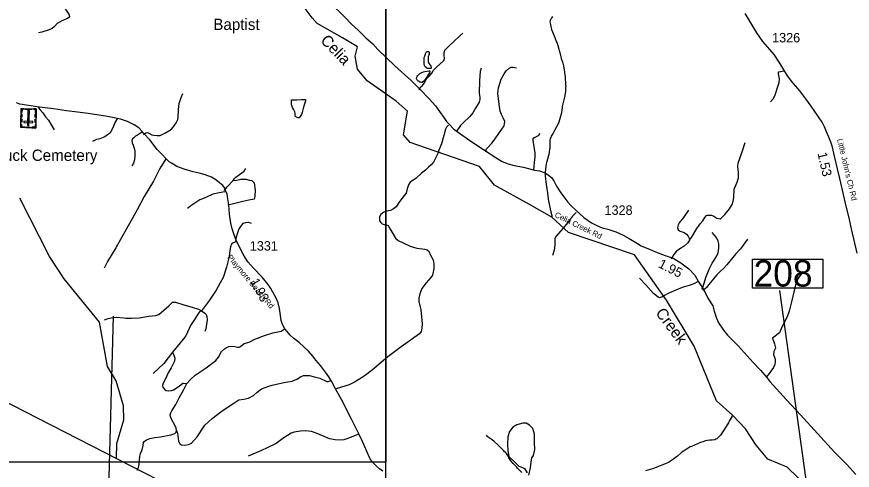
# Model space of a CAD drawing. Extents: x 1159738 to 1321356, y 736314 to 882035.
# Drawn here: x 1208685 to 1219753, y 778002 to 784003 of the extents above; entities that cross this region are included whole.
import ezdxf

# ---------------------------------------------------------------- set-up
doc = ezdxf.new("R2010")
doc.units = 0
for name, color, linetype in [('Exist Boundary Political CountyLine', 7, 'Continuous'), ('Exist Cultural Cemetery CELL', 7, 'Continuous'), ('Exist Cultural Cemetery Label', 7, 'Continuous'), ('Exist Cultural Church Label', 7, 'Continuous'), ('Exist Hydrographic Creek Single Shore', 7, 'Continuous'), ('Exist Hydrographic Creek Single Shore Label', 7, 'Continuous'), ('Exist Hydrographic Misc Water Feature', 7, 'Continuous'), ('Exist Road Non-System Type 51', 7, 'Continuous'), ('Exist Road Secondary Mileage Hundredths English Label', 7, 'Continuous'), ('Exist Road Secondary Structure Standard Bridge Number Label', 7, 'Continuous'), ('Exist Road Secondary Type 51 Attributed', 7, 'Continuous'), ('Exist Road Secondary Type 51 Label', 7, 'Continuous'), ('Exist Road Secondary Type 51 Number Label', 7, 'Continuous'), ('Map Preparation Inset Cut Line', 7, 'Continuous'), ('Map Preparation Longitude Latitude Lines', 7, 'Continuous')]:
    doc.layers.add(name, color=color, linetype=linetype)

msp = doc.modelspace()

# ---------------------------------------------------------------- linework, layer by layer
at = {"layer": 'Exist Boundary Political CountyLine'}
msp.add_lwpolyline([(1221685, 768580), (1219889, 769468), (1217945, 774092), (1206157, 780126), (1197315, 784354)], dxfattribs=at)
at = {"layer": 'Exist Cultural Cemetery CELL'}
for points in [[(1208937, 782530), (1208738, 782535), (1208744, 782789), (1208943, 782784)], [(1208777, 782789), (1208777, 782777), (1208755, 782778), (1208754, 782737), (1208743, 782738), (1208744, 782789)], [(1208886, 782774), (1208801, 782777), (1208801, 782788), (1208886, 782786)], [(1208910, 782785), (1208910, 782774), (1208932, 782773), (1208931, 782733), (1208942, 782733), (1208943, 782784)], [(1208754, 782717), (1208753, 782674), (1208741, 782674), (1208742, 782717)], [(1208829, 782562), (1208847, 782561), (1208852, 782764), (1208834, 782765)], [(1208942, 782715), (1208940, 782671), (1208929, 782672), (1208930, 782715)], [(1208739, 782578), (1208750, 782578), (1208749, 782546), (1208790, 782545), (1208790, 782534), (1208738, 782535)], [(1208752, 782651), (1208751, 782608), (1208740, 782608), (1208741, 782651)], [(1208898, 782599), (1208898, 782618), (1208781, 782621), (1208780, 782602)], [(1208938, 782573), (1208927, 782574), (1208926, 782541), (1208885, 782542), (1208885, 782531), (1208937, 782530)], [(1208940, 782647), (1208939, 782604), (1208927, 782604), (1208928, 782648)], [(1208863, 782532), (1208811, 782533), (1208811, 782544), (1208863, 782543)]]:
    msp.add_lwpolyline(points, close=True, dxfattribs=at)
at = {"layer": 'Exist Hydrographic Creek Single Shore'}
for points in [[(1212599, 783989), (1212519, 784096), (1212430, 784222), (1212427, 784288), (1212400, 784408), (1212418, 784549)], [(1219041, 777899), (1218890, 778042), (1218634, 778149), (1218481, 778332), (1218340, 778550), (1218168, 778730), (1217954, 778922), (1217660, 779644), (1217294, 780252), (1216867, 780851), (1215993, 781149), (1215772, 781352), (1215476, 781519), (1215012, 781772), (1214815, 782022), (1213897, 782338), (1213808, 782439), (1213861, 782753), (1213712, 782886), (1213327, 783154), (1213198, 783308), (1213169, 783481), (1213201, 783606), (1213000, 783722), (1212664, 783912), (1212599, 783989)]]:
    msp.add_lwpolyline(points, dxfattribs=at)
at = {"layer": 'Exist Hydrographic Misc Water Feature'}
for points in [[(1215782, 784007), (1215774, 783993), (1215763, 783977), (1215759, 783969), (1215753, 783951), (1215748, 783934), (1215750, 783917), (1215757, 783901)], [(1215757, 783901), (1215757, 783897), (1215770, 783835), (1215781, 783803), (1215799, 783757), (1215812, 783727), (1215837, 783666), (1215843, 783651), (1215848, 783636), (1215853, 783620), (1215867, 783574), (1215871, 783558), (1215882, 783510), (1215897, 783448), (1215902, 783433), (1215909, 783418), (1215918, 783387), (1215926, 783355), (1215932, 783323), (1215935, 783307), (1215942, 783260), (1215948, 783212), (1215956, 783099), (1215957, 783083), (1215956, 783066), (1215956, 783050), (1215955, 783033), (1215954, 783017), (1215949, 782985), (1215939, 782938), (1215912, 782813), (1215911, 782797), (1215906, 782765), (1215899, 782733), (1215887, 782686), (1215874, 782639), (1215864, 782609), (1215854, 782578), (1215815, 782506), (1215790, 782464), (1215774, 782435), (1215766, 782421), (1215759, 782406), (1215753, 782391), (1215748, 782359), (1215748, 782343), (1215747, 782326), (1215747, 782310), (1215747, 782294), (1215746, 782277), (1215746, 782261), (1215744, 782245), (1215740, 782212), (1215735, 782181), (1215731, 782165), (1215717, 782119), (1215707, 782089), (1215703, 782074), (1215699, 782058), (1215693, 782027), (1215686, 781946), (1215685, 781897), (1215698, 781785), (1215702, 781753), (1215705, 781737), (1215708, 781721), (1215710, 781705), (1215715, 781673), (1215721, 781626), (1215724, 781594), (1215731, 781562), (1215737, 781530), (1215744, 781499), (1215762, 781421), (1215774, 781373), (1215772, 781352)], [(1214089, 783480), (1214100, 783510), (1214108, 783528), (1214114, 783537), (1214121, 783542), (1214132, 783544), (1214141, 783542), (1214146, 783540), (1214148, 783536), (1214149, 783526), (1214148, 783515), (1214147, 783506), (1214142, 783492), (1214137, 783478), (1214134, 783464), (1214133, 783444), (1214133, 783413), (1214136, 783403), (1214140, 783391), (1214148, 783380), (1214162, 783363), (1214170, 783350), (1214174, 783339), (1214174, 783330), (1214173, 783320), (1214172, 783317), (1214168, 783317), (1214126, 783317), (1214123, 783319), (1214111, 783328), (1214096, 783340), (1214092, 783348), (1214087, 783359), (1214083, 783381), (1214080, 783399), (1214080, 783435), (1214082, 783455), (1214084, 783465), (1214089, 783480)], [(1213997, 783225), (1214012, 783239), (1214026, 783251), (1214051, 783266), (1214071, 783275), (1214092, 783278), (1214121, 783283), (1214147, 783287), (1214155, 783286), (1214157, 783275), (1214151, 783260), (1214134, 783232), (1214111, 783197), (1214096, 783174), (1214077, 783151), (1214062, 783136), (1214054, 783133), (1214045, 783134), (1214031, 783138), (1214009, 783148), (1214000, 783153), (1213994, 783160), (1213988, 783167), (1213984, 783176), (1213981, 783186), (1213981, 783194), (1213983, 783203), (1213988, 783214), (1213997, 783225)], [(1212325, 782902), (1212397, 782905), (1212455, 782907), (1212509, 782906), (1212508, 782890), (1212506, 782877), (1212497, 782846), (1212485, 782806), (1212474, 782769), (1212464, 782737), (1212455, 782707), (1212449, 782694), (1212440, 782682), (1212424, 782667), (1212418, 782665), (1212412, 782664), (1212401, 782668), (1212383, 782679), (1212377, 782684), (1212374, 782688), (1212374, 782695), (1212375, 782718), (1212373, 782727), (1212367, 782745), (1212361, 782761), (1212351, 782779), (1212338, 782802), (1212329, 782826), (1212324, 782836), (1212323, 782847), (1212325, 782902)], [(1210006, 778156), (1210012, 778356), (1210104, 778669), (1210100, 778853), (1210001, 779183), (1209889, 779376), (1209780, 779962), (1209312, 780536), (1209120, 780832), (1208724, 781602)], [(1218168, 778730), (1218160, 778716), (1218136, 778673), (1218128, 778659), (1218120, 778644), (1218112, 778630), (1218104, 778616), (1218043, 778520), (1218006, 778466), (1217996, 778453), (1217985, 778442), (1217973, 778431), (1217961, 778419), (1217946, 778413), (1217931, 778406), (1217899, 778401), (1217883, 778400), (1217867, 778398), (1217804, 778389), (1217788, 778384), (1217773, 778380), (1217743, 778367), (1217622, 778317), (1217607, 778310), (1217593, 778303), (1217578, 778295), (1217524, 778259), (1217510, 778250), (1217485, 778231), (1217436, 778188), (1217424, 778178), (1217386, 778148), (1217346, 778120), (1217318, 778104), (1217273, 778085), (1217243, 778074), (1217197, 778058), (1217153, 778037), (1217108, 778020), (1217014, 777994)], [(1215198, 778183), (1215171, 778223), (1215160, 778235), (1215148, 778247), (1215137, 778259), (1215125, 778270), (1215079, 778316), (1215068, 778328), (1215057, 778340), (1215008, 778383), (1214984, 778405), (1214971, 778415), (1214958, 778424), (1214944, 778433), (1214930, 778441), (1214917, 778451), (1214906, 778464)], [(1215376, 777970), (1215330, 778018), (1215319, 778030), (1215308, 778042), (1215297, 778054), (1215286, 778066), (1215274, 778078), (1215263, 778090), (1215230, 778126), (1215221, 778140), (1215213, 778154), (1215205, 778168), (1215198, 778183)]]:
    msp.add_lwpolyline(points, dxfattribs=at)
at = {"layer": 'Exist Road Non-System Type 51'}
for points in [[(1209221, 785242), (1209191, 785139), (1209161, 785011), (1209134, 784925), (1209139, 784802), (1209177, 784528), (1209215, 784373), (1209272, 784191), (1209351, 784066), (1209381, 784026), (1209384, 783998), (1209348, 783974), (1209283, 783950), (1209221, 783911), (1209186, 783872), (1209156, 783845), (1209115, 783828), (1209018, 783798), (1208971, 783788)], [(1214015, 783034), (1214040, 783076), (1214057, 783090), (1214085, 783129), (1214115, 783180), (1214157, 783224), (1214184, 783254), (1214206, 783294), (1214243, 783333), (1214343, 783424), (1214352, 783448), (1214347, 783495), (1214348, 783529), (1214357, 783560), (1214399, 783603), (1214556, 783750), (1214596, 783785)], [(1214898, 782215), (1214903, 782240), (1214909, 782256), (1214931, 782278), (1214978, 782328), (1215022, 782387), (1215082, 782470), (1215140, 782559), (1215148, 782587), (1215149, 782615), (1215130, 782663), (1215107, 782710), (1215089, 782751), (1215074, 782848), (1215058, 782991), (1215066, 783063), (1215102, 783176), (1215142, 783249), (1215170, 783289), (1215210, 783324), (1215235, 783334), (1215259, 783334), (1215304, 783327)], [(1214838, 783322), (1214823, 783277), (1214817, 783157), (1214810, 782988), (1214820, 782939), (1214819, 782908), (1214809, 782871), (1214763, 782791), (1214727, 782732), (1214686, 782684), (1214598, 782600), (1214565, 782563), (1214506, 782480)], [(1218671, 782878), (1218706, 782915), (1218730, 782967), (1218756, 783052), (1218784, 783133), (1218790, 783182), (1218778, 783226), (1218774, 783245), (1218777, 783272), (1218800, 783276), (1218845, 783289)], [(1210363, 782440), (1210376, 782453), (1210394, 782465), (1210415, 782469), (1210435, 782460), (1210476, 782438), (1210502, 782435), (1210543, 782431), (1210583, 782433), (1210645, 782461), (1210700, 782494), (1210736, 782517), (1210772, 782561), (1210798, 782601), (1210818, 782642), (1210823, 782672), (1210827, 782775), (1210838, 782856), (1210861, 782936), (1210886, 782985)], [(1208970, 782803), (1208996, 782769), (1209030, 782729), (1209064, 782676), (1209104, 782633), (1209138, 782582), (1209181, 782506)], [(1209691, 782358), (1209744, 782381), (1209790, 782391), (1209833, 782411), (1209850, 782419), (1209889, 782445), (1209925, 782473), (1209964, 782539), (1209990, 782602), (1210020, 782650)], [(1214406, 782570), (1214376, 782542), (1214364, 782514), (1214341, 782433), (1214310, 782319), (1214276, 782238), (1214261, 782194), (1214204, 782080), (1214176, 782045), (1214139, 782010), (1214101, 781973), (1214046, 781931), (1213978, 781866), (1213931, 781836), (1213898, 781813), (1213873, 781778), (1213856, 781727), (1213843, 781669), (1213815, 781638), (1213748, 781543), (1213713, 781489), (1213677, 781461), (1213636, 781441), (1213585, 781429), (1213548, 781415), (1213508, 781385), (1213492, 781354), (1213492, 781304), (1213506, 781282), (1213524, 781264), (1213550, 781252), (1213582, 781249), (1213605, 781240), (1213619, 781212), (1213657, 781147), (1213703, 781072), (1213738, 781044), (1213806, 781010), (1213896, 780968), (1213983, 780942), (1214091, 780928), (1214122, 780919), (1214143, 780900), (1214166, 780850), (1214199, 780784), (1214210, 780729), (1214208, 780668), (1214191, 780584), (1214171, 780551), (1214110, 780481), (1214050, 780405), (1214024, 780338), (1214010, 780277), (1214012, 780234), (1214036, 780125), (1214054, 779938), (1214052, 779882), (1214041, 779838), (1214021, 779806)], [(1210338, 782470), (1210285, 782436), (1210258, 782421), (1210236, 782402), (1210220, 782387), (1210209, 782364), (1210212, 782336), (1210229, 782302), (1210242, 782265), (1210251, 782225), (1210251, 782163), (1210245, 782110), (1210232, 782064), (1210208, 782030)], [(1215533, 781974), (1215539, 782021), (1215544, 782074), (1215552, 782147), (1215554, 782200), (1215539, 782280), (1215526, 782368), (1215527, 782387), (1215533, 782402), (1215571, 782418), (1215598, 782432), (1215617, 782456)], [(1217596, 781047), (1217625, 781080), (1217695, 781202), (1217736, 781263), (1217775, 781304), (1217801, 781345), (1217820, 781371), (1217834, 781376), (1217857, 781379), (1217886, 781376), (1217921, 781364), (1217959, 781338), (1217987, 781331), (1218005, 781329), (1218017, 781336), (1218064, 781386), (1218127, 781461), (1218163, 781519), (1218175, 781564), (1218184, 781611), (1218188, 781721), (1218226, 781815), (1218247, 781869), (1218245, 781940), (1218236, 782019), (1218242, 782066), (1218299, 782230), (1218334, 782340)], [(1210659, 782124), (1210582, 781995), (1210495, 781829), (1210374, 781624), (1210279, 781446), (1209996, 780946), (1209886, 780762), (1209845, 780675)], [(1211434, 781705), (1211473, 781753), (1211551, 781837), (1211564, 781857), (1211589, 781880), (1211635, 781914), (1211699, 781961), (1211720, 781995)], [(1211551, 781837), (1211601, 781840), (1211653, 781854), (1211690, 781854), (1211722, 781854), (1211763, 781842), (1211797, 781835), (1211829, 781803), (1211845, 781710), (1211840, 781624), (1211829, 781590), (1211760, 781574), (1211679, 781556), (1211540, 781521), (1211480, 781508)], [(1211441, 781687), (1211366, 781674), (1211284, 781653), (1211188, 781610), (1211111, 781578), (1210992, 781499), (1210949, 781467)], [(1217584, 781445), (1217516, 781347), (1217458, 781277), (1217446, 781249), (1217439, 781213), (1217446, 781185), (1217474, 781167), (1217528, 781146), (1217557, 781124), (1217580, 781099), (1217592, 781073), (1217596, 781047), (1217575, 781012), (1217528, 780967), (1217467, 780930), (1217422, 780895), (1217388, 780857), (1217354, 780794)], [(1216097, 781413), (1216049, 781362), (1215979, 781274), (1215923, 781205), (1215828, 781094), (1215812, 781064), (1215813, 781025), (1215813, 780980), (1215802, 780912), (1215780, 780845)], [(1211587, 781024), (1211596, 781089), (1211610, 781135), (1211626, 781189), (1211662, 781242), (1211689, 781272), (1211721, 781279), (1211753, 781283), (1211792, 781271)], [(1217761, 780397), (1217777, 780434), (1217814, 780553), (1217857, 780661), (1217897, 780742), (1217931, 780793), (1217960, 780839), (1217976, 780879), (1217984, 780939), (1217984, 780998), (1217975, 781034), (1217957, 781072), (1217929, 781111), (1217898, 781147)], [(1211587, 781024), (1211552, 781011), (1211531, 780993), (1211516, 780960), (1211509, 780909), (1211500, 780829), (1211465, 780689), (1211418, 780551), (1211380, 780480), (1211326, 780386), (1211238, 780251), (1211133, 780112)], [(1218365, 781059), (1218274, 780933), (1218206, 780862), (1218090, 780721), (1218053, 780678), (1218000, 780628), (1217956, 780585), (1217854, 780459), (1217823, 780420), (1217810, 780407), (1217772, 780382)], [(1219102, 780631), (1219057, 780574), (1219031, 780533), (1219007, 780471), (1218968, 780322), (1218952, 780246), (1218915, 780107), (1218890, 780032), (1218822, 779896), (1218791, 779818), (1218696, 779751)], [(1217702, 780493), (1217652, 780469), (1217592, 780445), (1217500, 780422), (1217394, 780378), (1217312, 780340), (1217265, 780314), (1217240, 780296), (1217199, 780282), (1217183, 780293), (1217122, 780340), (1217017, 780457), (1216934, 780544)], [(1209846, 779991), (1209894, 780009), (1209958, 780025), (1210003, 780028), (1210105, 780018), (1210131, 780014), (1210204, 780016), (1210308, 780019), (1210383, 780030), (1210434, 780039), (1210477, 780043), (1210527, 780050), (1210565, 780064), (1210698, 780178), (1210750, 780226), (1210766, 780228), (1210789, 780228), (1210900, 780191), (1211010, 780160), (1211092, 780132), (1211133, 780112)], [(1211133, 780112), (1211107, 780096), (1211076, 780055), (1211048, 780010), (1211030, 779984), (1210986, 779916), (1210929, 779790), (1210911, 779761), (1210750, 779564), (1210635, 779416), (1210492, 779284)], [(1211133, 780112), (1211178, 780082), (1211196, 780062), (1211205, 780037), (1211208, 779993), (1211192, 779873), (1211176, 779838)], [(1210940, 779151), (1210992, 779209), (1211049, 779258), (1211196, 779357), (1211324, 779452), (1211356, 779499), (1211399, 779574), (1211435, 779607), (1211464, 779627), (1211495, 779640), (1211531, 779644), (1211573, 779640), (1211609, 779630), (1211631, 779631), (1211649, 779640), (1211699, 779678), (1211765, 779697), (1211840, 779735), (1211969, 779785), (1212077, 779818), (1212187, 779844), (1212229, 779867)], [(1214021, 779806), (1213779, 779637), (1213601, 779502), (1213396, 779330), (1213289, 779248), (1213158, 779167), (1213088, 779133), (1212929, 779085), (1212899, 779073)], [(1218696, 779751), (1218724, 779676), (1218736, 779622), (1218732, 779609), (1218713, 779571), (1218711, 779532), (1218730, 779471), (1218732, 779435), (1218726, 779400), (1218711, 779360), (1218638, 779264), (1218607, 779228)], [(1210750, 779564), (1210771, 779511), (1210778, 779485), (1210773, 779447), (1210729, 779355), (1210690, 779291), (1210655, 779210), (1210623, 779152), (1210616, 779125), (1210622, 779100), (1210642, 779074), (1210666, 779059), (1210696, 779053), (1210736, 779056), (1210760, 779066), (1210836, 779116), (1210886, 779152), (1210896, 779155), (1210940, 779151)], [(1210801, 778528), (1210814, 778491), (1210829, 778386), (1210846, 778353), (1210868, 778337), (1210910, 778335), (1210962, 778341), (1211002, 778360), (1211076, 778445), (1211176, 778598), (1211275, 778687), (1211408, 778789), (1211559, 778890), (1211629, 778935), (1211694, 778944), (1211755, 778955), (1211822, 778990), (1211868, 779033), (1211928, 779080), (1212024, 779114), (1212070, 779128), (1212144, 779147), (1212250, 779168), (1212334, 779180), (1212366, 779192), (1212397, 779206), (1212444, 779240), (1212485, 779255), (1212523, 779257), (1212562, 779254), (1212612, 779242), (1212701, 779221), (1212794, 779178), (1212812, 779177), (1212836, 779187)], [(1210282, 778005), (1210296, 778039), (1210306, 778076), (1210315, 778190), (1210326, 778223), (1210347, 778274), (1210358, 778331), (1210363, 778367), (1210371, 778381), (1210406, 778405), (1210450, 778423), (1210513, 778434), (1210589, 778444), (1210725, 778471), (1210777, 778486), (1210797, 778505), (1210801, 778528), (1210799, 778558), (1210788, 778580), (1210730, 778686), (1210720, 778712), (1210719, 778735), (1210725, 778762), (1210740, 778789), (1210792, 778874), (1210837, 778958), (1210897, 779069), (1210934, 779139), (1210940, 779151)], [(1215467, 777939), (1215492, 778034), (1215499, 778111), (1215509, 778168), (1215529, 778198), (1215547, 778277), (1215544, 778367), (1215544, 778409), (1215544, 778479), (1215522, 778554), (1215477, 778598), (1215435, 778626), (1215390, 778626), (1215308, 778601), (1215258, 778574), (1215213, 778514), (1215189, 778444), (1215186, 778347), (1215189, 778258), (1215204, 778183), (1215293, 778098), (1215338, 778058), (1215383, 778039), (1215410, 778024), (1215447, 777969)], [(1213204, 778476), (1213135, 778450), (1213056, 778417), (1213019, 778404), (1212978, 778398), (1212901, 778404), (1212830, 778417), (1212757, 778448), (1212650, 778494), (1212590, 778516), (1212504, 778522), (1212442, 778519), (1212360, 778508), (1212320, 778491), (1212210, 778420), (1212120, 778358), (1212001, 778298), (1211929, 778264), (1211752, 778190)]]:
    msp.add_lwpolyline(points, dxfattribs=at)
at = {"layer": 'Exist Road Secondary Structure Standard Bridge Number Label'}
msp.add_line((1219144, 777876), (1218795, 780379), dxfattribs=at)
msp.add_lwpolyline([(1218433, 780796), (1219362, 780796), (1219362, 780412), (1218433, 780412)], close=True, dxfattribs=at)
at = {"layer": 'Exist Road Secondary Type 51 Attributed'}
for points in [[(1212827, 784196), (1213031, 783996), (1213119, 783905), (1213208, 783825), (1213310, 783723), (1213402, 783644), (1213468, 783567), (1213693, 783352), (1213909, 783157), (1214029, 783039), (1214150, 782918), (1214233, 782822), (1214285, 782748), (1214342, 782671), (1214380, 782617), (1214416, 782575), (1214464, 782526), (1214489, 782504), (1214519, 782482), (1214687, 782366), (1214870, 782246), (1215058, 782124), (1215115, 782087), (1215193, 782058), (1215273, 782036), (1215398, 782013), (1215542, 781974), (1215609, 781962), (1215684, 781937), (1215729, 781908), (1215769, 781876), (1215798, 781832), (1215837, 781763), (1215891, 781674), (1215944, 781603), (1215985, 781548), (1216024, 781503), (1216097, 781437), (1216198, 781347), (1216298, 781274), (1216368, 781239), (1216442, 781208), (1216515, 781190), (1216619, 781157), (1216718, 781113), (1216797, 781068), (1216907, 781001), (1216956, 780973), (1217076, 780924), (1217145, 780894), (1217275, 780845), (1217380, 780807), (1217482, 780745), (1217586, 780668), (1217666, 780585), (1217717, 780494), (1217786, 780387), (1217840, 780279), (1217905, 780177), (1217925, 780106), (1217954, 780015), (1217983, 779951), (1218049, 779857), (1218099, 779788), (1218243, 779648), (1218440, 779427), (1218538, 779324), (1218620, 779227), (1218662, 779178), (1218883, 778935), (1219068, 778734), (1219518, 778241), (1219685, 778072), (1219798, 777945)], [(1219818, 780875), (1219744, 781198), (1219706, 781358), (1219674, 781495), (1219586, 781863), (1219556, 781990), (1219518, 782159), (1219489, 782277), (1219468, 782344), (1219441, 782411), (1219412, 782480), (1219383, 782545), (1219352, 782606), (1219210, 782818), (1219136, 782918), (1219057, 783021), (1218950, 783151), (1218898, 783218), (1218859, 783279), (1218821, 783344), (1218783, 783403), (1218718, 783505), (1218659, 783570), (1218566, 783677), (1218489, 783790), (1218398, 783943), (1218332, 784044)], [(1213535, 777990), (1213492, 778019), (1213451, 778056), (1213426, 778082), (1213397, 778111), (1213368, 778154), (1213341, 778211), (1213313, 778270), (1213264, 778382), (1213216, 778482), (1213159, 778597), (1213114, 778688), (1213064, 778786), (1213007, 778899), (1212908, 779080), (1212858, 779171), (1212817, 779240), (1212777, 779299), (1212709, 779386), (1212646, 779459), (1212605, 779513), (1212549, 779577), (1212490, 779637), (1212425, 779694), (1212357, 779746), (1212307, 779791), (1212267, 779838), (1212236, 779874), (1212204, 779929), (1212186, 779982), (1212178, 780051), (1212166, 780140), (1212146, 780215), (1212123, 780278), (1212095, 780328), (1212052, 780408), (1212014, 780460), (1211935, 780557), (1211822, 780677), (1211744, 780761), (1211714, 780806), (1211684, 780861), (1211596, 781031), (1211562, 781128), (1211540, 781196), (1211520, 781272), (1211505, 781391), (1211493, 781515), (1211482, 781593), (1211474, 781656), (1211455, 781694), (1211444, 781730), (1211414, 781770), (1211372, 781806), (1211323, 781844), (1211263, 781879), (1211182, 781910), (1211103, 781934), (1211023, 781950), (1210902, 781985), (1210804, 782023), (1210756, 782051), (1210736, 782066), (1210706, 782084), (1210662, 782127), (1210613, 782179), (1210547, 782247), (1210448, 782372), (1210364, 782464), (1210346, 782483), (1210302, 782532), (1210241, 782572), (1210152, 782617), (1210061, 782646), (1209976, 782666), (1209887, 782684), (1209633, 782721), (1209492, 782739), (1209342, 782758), (1209170, 782782), (1208987, 782806), (1208870, 782822), (1208809, 782831), (1208758, 782840), (1208727, 782848), (1208680, 782865)]]:
    msp.add_lwpolyline(points, dxfattribs=at)
at = {"layer": 'Map Preparation Inset Cut Line'}
for points in [[(1213575, 811005), (1289258, 811005), (1289258, 782300), (1274049, 782297), (1274049, 766757), (1213575, 766757)], [(1213575, 778109), (1194108, 778109), (1194108, 805981), (1213575, 805981)]]:
    msp.add_lwpolyline(points, close=True, dxfattribs=at)
at = {"layer": 'Map Preparation Longitude Latitude Lines'}
msp.add_line((1209727, 771058), (1209968, 780039), dxfattribs=at)

# ---------------------------------------------------------------- texts
at = {"layer": 'Exist Cultural Cemetery Label'}
msp.add_text('Houck Cemetery', height=150, dxfattribs=at).set_placement((1208260, 782095))
at = {"layer": 'Exist Cultural Church Label'}
msp.add_text('Baptist', height=150, rotation=0, dxfattribs=at).set_placement((1211289, 783827))
at = {"layer": 'Exist Hydrographic Creek Single Shore Label'}
for s, rotation, p in [('Celia', 314.1388, (1212699, 783679)), ('Creek', 306.6153, (1217140, 780082))]:
    msp.add_text(s, height=150, rotation=rotation, dxfattribs=at).set_placement(p)
at = {"layer": 'Exist Road Secondary Mileage Hundredths English Label'}
for s, rotation, p in [('1.53', 282.6739, (1219292, 782196)), ('1.95', 333.1823, (1217173, 780692)), ('1.93', 298.2833, (1211772, 780502))]:
    msp.add_text(s, height=125, rotation=rotation, dxfattribs=at).set_placement(p)
at = {"layer": 'Exist Road Secondary Structure Standard Bridge Number Label'}
msp.add_text('208', height=350, dxfattribs=at).set_placement((1218446, 780432))
at = {"layer": 'Exist Road Secondary Type 51 Label'}
for s, rotation, p in [("Little John's Ch Rd", 283.42, (1219551, 782379)), ('Celia Creek Rd', 333.965, (1215804, 781357)), ('Playmore Beach Rd', 310.1926, (1211469, 780815))]:
    msp.add_text(s, height=75, rotation=rotation, dxfattribs=at).set_placement(p)
at = {"layer": 'Exist Road Secondary Type 51 Number Label'}
for s, p in [('1326', (1218691, 783663)), ('1328', (1216471, 781381)), ('1331', (1211772, 780908))]:
    msp.add_text(s, height=125, dxfattribs=at).set_placement(p)

doc.saveas('drawing.dxf')
